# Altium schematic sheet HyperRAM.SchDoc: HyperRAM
size A4; CompanyName: STMicroelectronics; Organization: Microcontrollers Division; DocumentNumber: 14; SheetNumber: 10; SheetTotal: 19
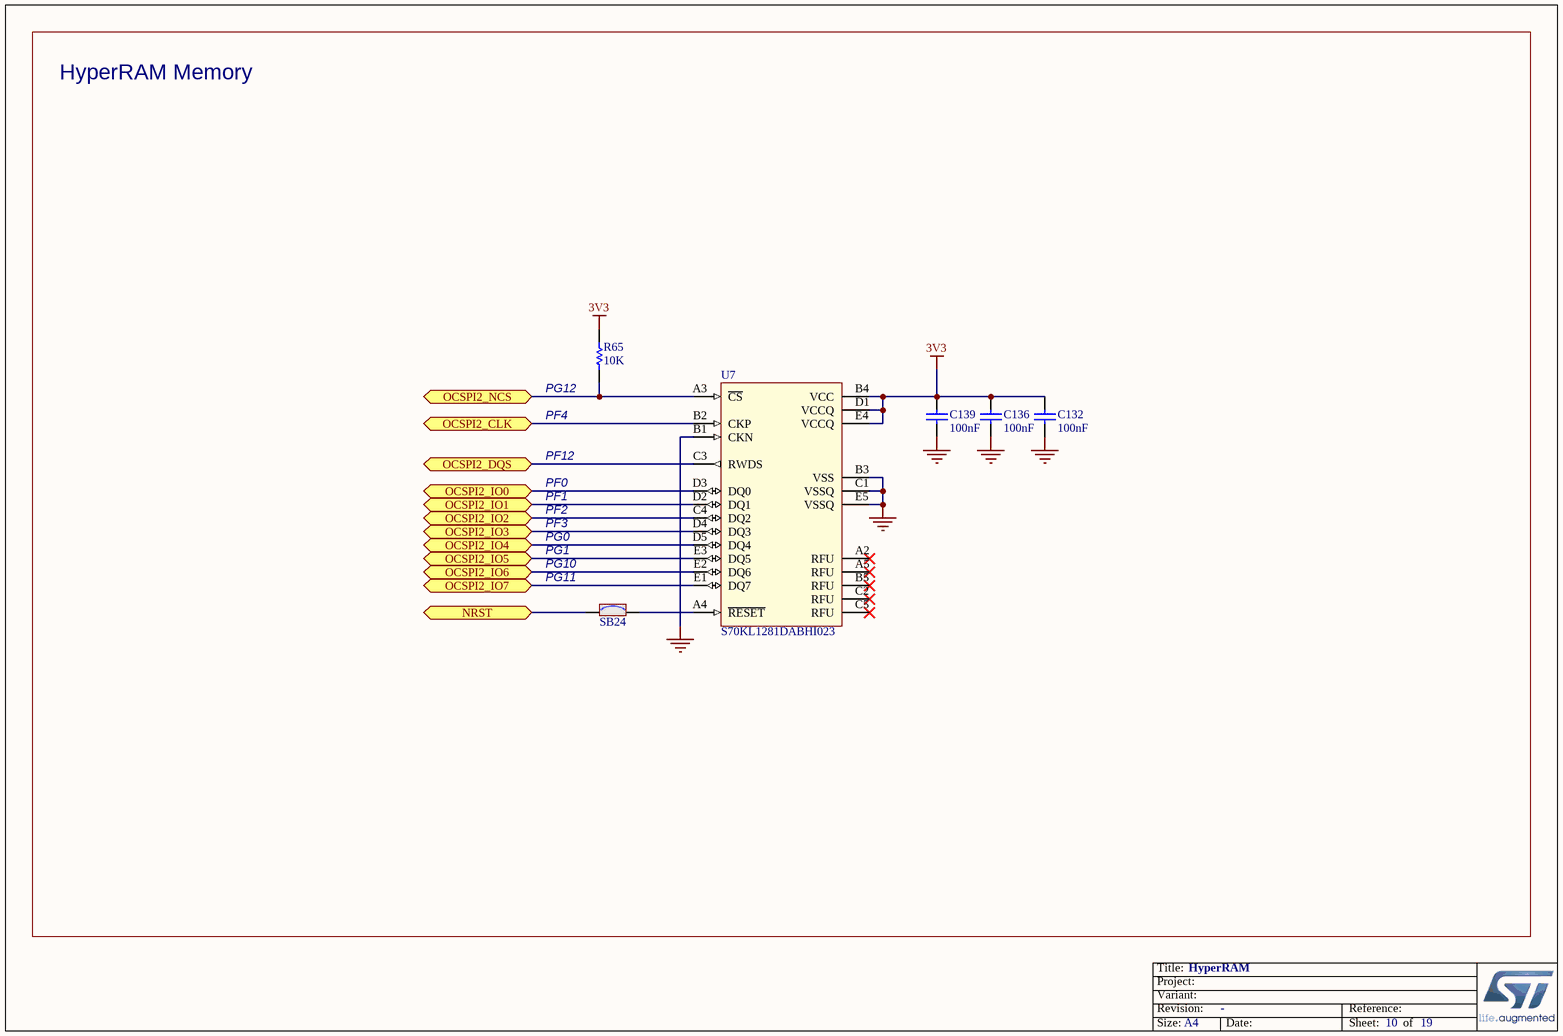
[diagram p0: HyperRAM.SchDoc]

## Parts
C132  value 100nF  [C0402]  (hidden comment: Capacitor)
C136  value 100nF  [C0402]  (hidden comment: Capacitor)
C139  value 100nF  [C0402]  (hidden comment: Capacitor)
R65  value 10K  [R0402]  (hidden comment: Resistor)
SB24  SB_ON  [SOLDER-BRIDGE_R0603-0R]  (value not drawn)
U7  S70KL1281DABHI023  [ICC_FBGA24_5X5-BALL-ARRAY_6X8_P1]

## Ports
NRST (bidir), OCSPI2_CLK (bidir), OCSPI2_DQS (bidir), OCSPI2_IO0 (bidir), OCSPI2_IO1 (bidir), OCSPI2_IO2 (bidir), OCSPI2_IO3 (bidir), OCSPI2_IO4 (bidir), OCSPI2_IO5 (bidir), OCSPI2_IO6 (bidir), OCSPI2_IO7 (bidir), OCSPI2_NCS (bidir)

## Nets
3V3: C132.2 C136.2 C139.2 R65.2 U7.B4(VCC) U7.D1(VCCQ) U7.E4(VCCQ)
GND: C132.1 C136.1 C139.1 U7.B1(CKN) U7.B3(VSS) U7.C1(VSSQ) U7.E5(VSSQ)
NRST: SB24.1 ; port NRST
OCSPI2_CLK: U7.B2(CKP) ; port OCSPI2_CLK
OCSPI2_DQS: U7.C3(RWDS) ; port OCSPI2_DQS
OCSPI2_IO0: U7.D3(DQ0) ; port OCSPI2_IO0
OCSPI2_IO1: U7.D2(DQ1) ; port OCSPI2_IO1
OCSPI2_IO2: U7.C4(DQ2) ; port OCSPI2_IO2
OCSPI2_IO3: U7.D4(DQ3) ; port OCSPI2_IO3
OCSPI2_IO4: U7.D5(DQ4) ; port OCSPI2_IO4
OCSPI2_IO5: U7.E3(DQ5) ; port OCSPI2_IO5
OCSPI2_IO6: U7.E2(DQ6) ; port OCSPI2_IO6
OCSPI2_IO7: U7.E1(DQ7) ; port OCSPI2_IO7
OCSPI2_NCS: R65.1 U7.A3(~{CS}) ; port OCSPI2_NCS
NetSB24_2: SB24.2 U7.A4(~{RESET})

Not connected (* = marked no-connect by the designer): U7 A2(RFU)* A5(RFU)* B5(RFU)* C2(RFU)* C5(RFU)*

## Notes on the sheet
- HyperRAM Memory
- (near R65) PG12
- PF4
- PF12
- PF0
- PF1
- PF2
- PF3
- PG0
- PG1
- (near SB24) PG10
- (near SB24) PG11

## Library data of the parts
C132 C136 C139 = MCD-00102: Capacitor, MLCC, 100nF, 16V, X7R, 10%, 0402, T=0,5mm; Manufacturer_Part_Number: CC0402KRX7R7BB104; Manufacturer: YAGEO; Alternate_Manufacturer_Part_Number: GCM155R71C104KA55D; Alternate_Manufacturer: MURATA; ECCN_US: EAR99; ECCN_EU: NEC; Provided_By: SUBCO
R65 = MCD-00053: Resistor,10K,0402,1%,1/16W; Manufacturer_Part_Number: RC0402FR-0710KL; Manufacturer: YAGEO; ECCN_US: EAR99; ECCN_EU: NEC; Provided_By: SUBCO
SB24 = MCD-00071: Solder Bridge ON; Part_Type: Mechanical; Manufacturer_Part_Number: RC0603JR-070RL; Manufacturer: YAGEO; Provided_By: SUBCO
U7 = MCD-01824: Memory, HyperRAM,128Mb,100MHz,3V,BGA24; Part_Type: IC; Manufacturer: CYPRESS; Provided_By: SUBCO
